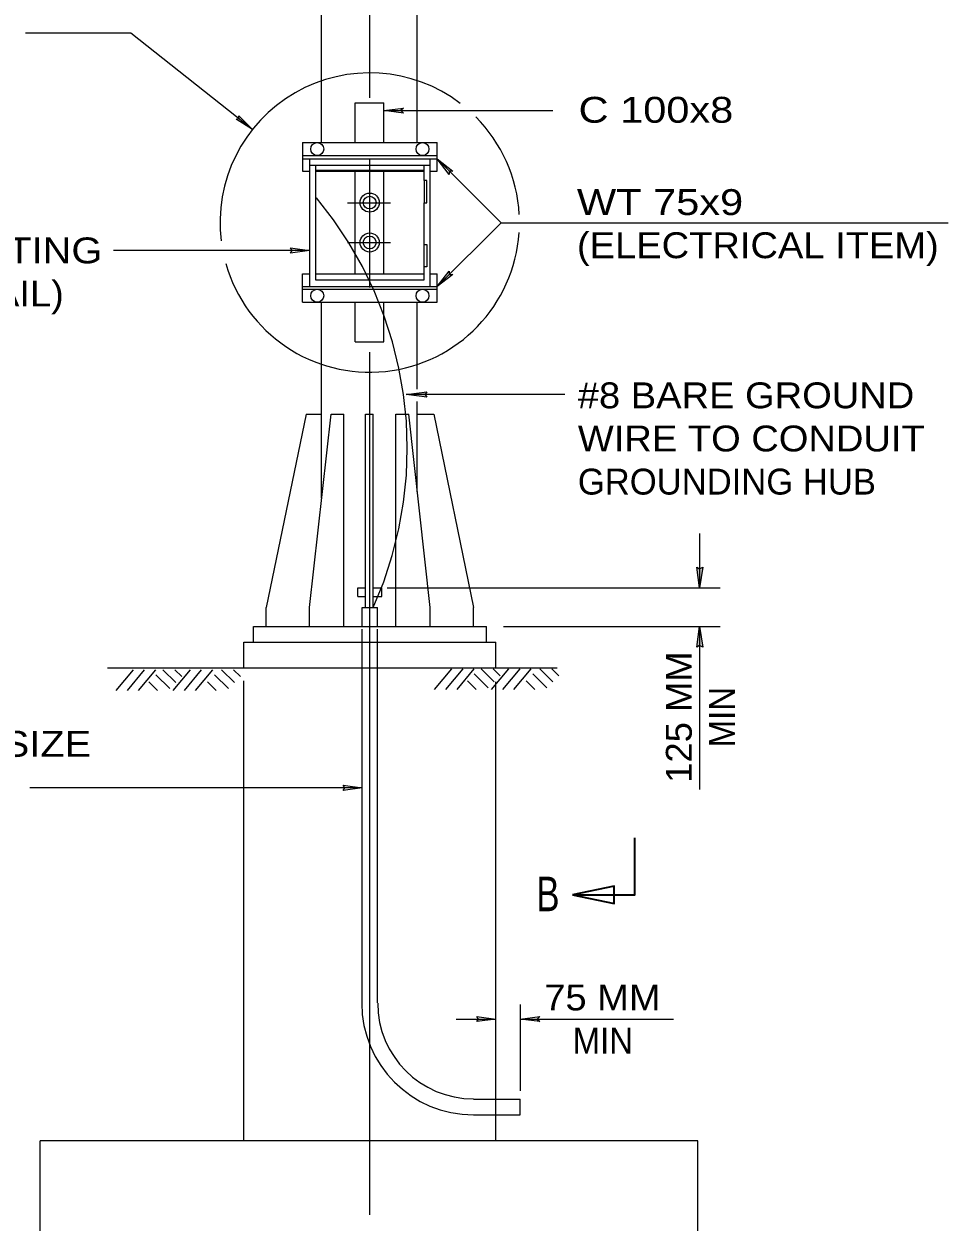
# Model space of a CAD drawing. Extents: x 312601.858 to 312602.699, y 144420.109 to 144420.704.
# Drawn here: x 312601.9631 to 312602.0702, y 144420.232 to 144420.3709 of the extents above; entities that cross this region are included whole.
import ezdxf
from ezdxf.enums import TextEntityAlignment as Align

# ---------------------------------------------------------------- set-up
doc = ezdxf.new("R2010")
doc.units = 0
doc.header["$LTSCALE"] = 0.0012
doc.linetypes.add('LONG_DASH_SHORT_DASH', pattern=[9.9, 6, -1.2, 1.5, -1.2])
doc.linetypes.add('LONG_DASHED', pattern=[7.5, 6, -1.5])
for name, color, linetype, lineweight in [('1', 7, 'Continuous', 25), ('2', 7, 'Continuous', 25), ('39', 7, 'Continuous', 13)]:
    doc.layers.add(name, color=color, linetype=linetype, lineweight=lineweight)

msp = doc.modelspace()

# ---------------------------------------------------------------- hatches: boundary and pattern name
at = {"layer": '39'}
for points in [[(312602.0096, 144420.3279), (312602.0098, 144420.3276), (312602.0074, 144420.3279), (312602.0098, 144420.3282)], [(312602.0414, 144420.3077), (312602.0418, 144420.3079), (312602.0414, 144420.3055), (312602.0411, 144420.3079)], [(312602.0414, 144420.2988), (312602.0411, 144420.2986), (312602.0414, 144420.301), (312602.0418, 144420.2986)]]:
    msp.add_hatch(color=256, dxfattribs=at).paths.add_polyline_path(points)

# ---------------------------------------------------------------- linework, layer by layer
at = {"layer": '1', "linetype": 'LONG_DASH_SHORT_DASH', "lineweight": 13}
for p, q in [((312602.0032, 144420.3623), (312602.0032, 144420.3835)), ((312602.0032, 144420.3403), (312602.0032, 144420.3552)), ((312602.0006, 144420.3501), (312602.0056, 144420.3501)), ((312602.0006, 144420.3455), (312602.0056, 144420.3455)), ((312602.0032, 144420.2328), (312602.0032, 144420.3338))]:
    msp.add_line(p, q, dxfattribs=at)
at = {"layer": '1'}
for p, q in [((312601.9976, 144420.3571), (312601.9976, 144420.3784)), ((312602.0087, 144420.3571), (312602.0087, 144420.3784)), ((312602.0015, 144420.3617), (312602.0048, 144420.3617)), ((312602.0015, 144420.3571), (312602.0015, 144420.3617)), ((312602.0048, 144420.3571), (312602.0048, 144420.3617)), ((312601.9954, 144420.3571), (312602.011, 144420.3571)), ((312601.9954, 144420.3571), (312601.9954, 144420.3538)), ((312602.011, 144420.3538), (312602.011, 144420.3571)), ((312601.9954, 144420.3556), (312602.011, 144420.3556)), ((312601.9954, 144420.3552), (312602.011, 144420.3552)), ((312601.9962, 144420.3552), (312601.9962, 144420.3404)), ((312602.0102, 144420.3404), (312602.0102, 144420.3552)), ((312601.9954, 144420.3538), (312601.9962, 144420.3538)), ((312601.9962, 144420.3545), (312602.0102, 144420.3545)), ((312601.9969, 144420.3545), (312601.9969, 144420.3412)), ((312601.9969, 144420.3538), (312602.0095, 144420.3538)), ((312602.0095, 144420.3527), (312602.0095, 144420.3545)), ((312602.0102, 144420.3538), (312602.011, 144420.3538)), ((312601.9954, 144420.3386), (312601.9954, 144420.3419)), ((312601.9954, 144420.3419), (312601.9962, 144420.3419)), ((312601.9969, 144420.3412), (312602.0095, 144420.3412)), ((312602.0102, 144420.3419), (312602.011, 144420.3419)), ((312602.011, 144420.3386), (312602.011, 144420.3419)), ((312601.9954, 144420.3404), (312602.011, 144420.3404)), ((312601.9954, 144420.3401), (312602.011, 144420.3401)), ((312601.9954, 144420.3386), (312602.011, 144420.3386)), ((312601.9976, 144420.3159), (312601.9976, 144420.3386)), ((312602.0015, 144420.334), (312602.0015, 144420.3386)), ((312602.0048, 144420.334), (312602.0048, 144420.3386)), ((312602.0087, 144420.3285), (312602.0087, 144420.3386)), ((312602.0015, 144420.334), (312602.0048, 144420.334)), ((312602.0087, 144420.3166), (312602.0087, 144420.3271)), ((312601.9958, 144420.3256), (312601.9912, 144420.3032)), ((312601.9958, 144420.3256), (312601.9976, 144420.3256)), ((312601.9987, 144420.3256), (312602.0002, 144420.3256)), ((312602.0002, 144420.301), (312602.0002, 144420.3256)), ((312602.0027, 144420.3256), (312602.0036, 144420.3256)), ((312602.0027, 144420.3032), (312602.0027, 144420.3256)), ((312602.0036, 144420.3032), (312602.0036, 144420.3256)), ((312602.0062, 144420.301), (312602.0062, 144420.3256)), ((312602.0062, 144420.3256), (312602.0077, 144420.3256)), ((312602.0087, 144420.3256), (312602.0106, 144420.3256)), ((312602.0106, 144420.3256), (312602.0152, 144420.3032)), ((312602.0018, 144420.3045), (312602.0018, 144420.3055)), ((312602.0018, 144420.3055), (312602.0027, 144420.3055)), ((312602.0036, 144420.3055), (312602.0046, 144420.3055)), ((312602.0046, 144420.3045), (312602.0046, 144420.3055)), ((312602.0018, 144420.3045), (312602.0027, 144420.3045)), ((312602.0036, 144420.3045), (312602.0046, 144420.3045)), ((312601.9912, 144420.301), (312601.9912, 144420.3032)), ((312601.9962, 144420.301), (312601.9962, 144420.3032)), ((312602.0023, 144420.3032), (312602.0041, 144420.3032)), ((312602.0023, 144420.301), (312602.0023, 144420.3032)), ((312602.0041, 144420.301), (312602.0041, 144420.3032)), ((312602.0102, 144420.301), (312602.0102, 144420.3032)), ((312602.0152, 144420.301), (312602.0152, 144420.3032)), ((312601.9897, 144420.301), (312602.0167, 144420.301)), ((312601.9897, 144420.2992), (312601.9897, 144420.301)), ((312602.0167, 144420.2992), (312602.0167, 144420.301)), ((312601.9886, 144420.2992), (312602.0178, 144420.2992)), ((312601.9886, 144420.2962), (312601.9886, 144420.2992)), ((312602.0178, 144420.2962), (312602.0178, 144420.2992)), ((312601.9728, 144420.2962), (312602.0249, 144420.2962))]:
    msp.add_line(p, q, dxfattribs=at)
at = {"layer": '1', "lineweight": 13}
for p, q in [((312601.9755, 144420.3698), (312601.9633, 144420.3698)), ((312601.9896, 144420.3586), (312601.9755, 144420.3698)), ((312602.0048, 144420.3608), (312602.0244, 144420.3608)), ((312602.011, 144420.3552), (312602.0184, 144420.3478)), ((312602.011, 144420.3404), (312602.0184, 144420.3478)), ((312602.0184, 144420.3478), (312602.0702, 144420.3478)), ((312601.9962, 144420.3446), (312601.9735, 144420.3446)), ((312602.0258, 144420.3279), (312602.0074, 144420.3279)), ((312602.0414, 144420.3118), (312602.0414, 144420.3055)), ((312602.0052, 144420.3055), (312602.0438, 144420.3055)), ((312602.0187, 144420.301), (312602.0438, 144420.301)), ((312602.0414, 144420.301), (312602.0414, 144420.2821)), ((312601.9738, 144420.2936), (312601.9758, 144420.296)), ((312601.9751, 144420.2936), (312601.9771, 144420.296)), ((312601.9764, 144420.2936), (312601.9784, 144420.296)), ((312601.9784, 144420.2954), (312601.98, 144420.2938)), ((312601.9792, 144420.296), (312601.9807, 144420.2945)), ((312601.9804, 144420.2936), (312601.9824, 144420.296)), ((312601.9806, 144420.296), (312601.9814, 144420.2952)), ((312601.9817, 144420.2936), (312601.9837, 144420.296)), ((312601.983, 144420.2936), (312601.985, 144420.296)), ((312601.9852, 144420.2954), (312601.9868, 144420.2938)), ((312601.986, 144420.296), (312601.9875, 144420.2945)), ((312601.9874, 144420.296), (312601.9882, 144420.2952)), ((312602.0107, 144420.2937), (312602.0127, 144420.2961)), ((312602.012, 144420.2937), (312602.014, 144420.2961)), ((312602.0133, 144420.2937), (312602.0153, 144420.2961)), ((312602.0153, 144420.2955), (312602.0169, 144420.2939)), ((312602.0161, 144420.2961), (312602.0176, 144420.2946)), ((312602.0173, 144420.2937), (312602.0193, 144420.2961)), ((312602.0175, 144420.2961), (312602.0183, 144420.2953)), ((312602.0186, 144420.2937), (312602.0206, 144420.2961)), ((312602.0199, 144420.2937), (312602.0219, 144420.2961)), ((312602.0221, 144420.2955), (312602.0237, 144420.2939)), ((312602.0229, 144420.2961), (312602.0244, 144420.2946)), ((312602.0243, 144420.2961), (312602.0251, 144420.2953)), ((312601.9776, 144420.2946), (312601.9786, 144420.2936)), ((312601.9844, 144420.2946), (312601.9854, 144420.2936)), ((312602.0145, 144420.2947), (312602.0155, 144420.2937)), ((312602.0213, 144420.2947), (312602.0223, 144420.2937)), ((312602.0023, 144420.2823), (312601.9638, 144420.2823)), ((312602.0206, 144420.2572), (312602.0206, 144420.2472)), ((312602.0132, 144420.2555), (312602.0178, 144420.2555)), ((312602.0206, 144420.2555), (312602.0384, 144420.2555))]:
    msp.add_line(p, q, dxfattribs=at)
at = {"layer": '1', "linetype": 'LONG_DASHED'}
msp.add_line((312601.9969, 144420.3539), (312602.0095, 144420.3539), dxfattribs=at)
at = {"layer": '1', "linetype": 'LONG_DASHED', "lineweight": 13}
for p, q in [((312602.0015, 144420.3419), (312602.0015, 144420.3538)), ((312602.0048, 144420.3419), (312602.0048, 144420.3538)), ((312601.9969, 144420.3419), (312602.0095, 144420.3419)), ((312602.0023, 144420.2574), (312602.0023, 144420.3007)), ((312602.0041, 144420.2574), (312602.0041, 144420.3007)), ((312601.9886, 144420.2414), (312601.9886, 144420.2947)), ((312602.0178, 144420.2414), (312602.0178, 144420.2946)), ((312602.0152, 144420.2462), (312602.0206, 144420.2462)), ((312602.0206, 144420.2444), (312602.0206, 144420.2462)), ((312602.0152, 144420.2444), (312602.0206, 144420.2444)), ((312601.965, 144420.2234), (312601.965, 144420.2414)), ((312602.0412, 144420.2414), (312601.965, 144420.2414))]:
    msp.add_line(p, q, dxfattribs=at)
at = {"layer": '1', "lineweight": 13}
for points in [[(312602.0071, 144420.3605), (312602.0048, 144420.3608), (312602.0071, 144420.3611), (312602.0068, 144420.3608)], [(312601.988, 144420.3602), (312601.9896, 144420.3586), (312601.9877, 144420.3598), (312601.988, 144420.3599)], [(312602.0124, 144420.3534), (312602.011, 144420.3552), (312602.0128, 144420.3538), (312602.0124, 144420.3538)], [(312601.994, 144420.3449), (312601.9962, 144420.3446), (312601.994, 144420.3443), (312601.9942, 144420.3446)], [(312602.0128, 144420.3418), (312602.011, 144420.3404), (312602.0124, 144420.3422), (312602.0124, 144420.3418)], [(312602.0001, 144420.2826), (312602.0023, 144420.2823), (312602.0001, 144420.282), (312602.0003, 144420.2823)], [(312602.0156, 144420.2558), (312602.0178, 144420.2555), (312602.0156, 144420.2552), (312602.0158, 144420.2555)], [(312602.0229, 144420.2552), (312602.0206, 144420.2555), (312602.0229, 144420.2558), (312602.0226, 144420.2555)]]:
    msp.add_lwpolyline(points, close=True, dxfattribs=at)
at = {"layer": '1'}
msp.add_lwpolyline([(312602.0095, 144420.3412), (312602.0095, 144420.3501), (312602.0098, 144420.3501), (312602.0098, 144420.3527), (312602.0095, 144420.3527), (312602.0095, 144420.3501)], dxfattribs=at)
msp.add_lwpolyline([(312602.0095, 144420.3453), (312602.0098, 144420.3453), (312602.0098, 144420.3427), (312602.0095, 144420.3427)], close=True, dxfattribs=at)
at = {"layer": '1', "linetype": 'LONG_DASHED', "lineweight": 13}
msp.add_lwpolyline([(312601.965, 144420.2234), (312602.0412, 144420.2234), (312602.0412, 144420.2414)], dxfattribs=at)
at = {"layer": '1'}
for centre, radius in [((312601.9971, 144420.35635), 0.00075), ((312602.0093, 144420.35635), 0.00075), ((312602.003181, 144420.350142), 0.00111), ((312602.003181, 144420.350142), 0.00074), ((312602.003181, 144420.345517), 0.00111), ((312602.003181, 144420.345517), 0.00074), ((312601.9971, 144420.33935), 0.00075), ((312602.0093, 144420.33935), 0.00075)]:
    msp.add_circle(centre, radius, dxfattribs=at)
at = {"layer": '1', "lineweight": 13}
for start, end in [(52.76429, 187.07844), (3.14562, 44.8773), (195.9314, 356.15117)]:
    msp.add_arc((312602.003181, 144420.34783), 0.017351, start, end, dxfattribs=at)
at = {"layer": '1', "linetype": 'LONG_DASHED'}
msp.add_arc((312601.962274, 144420.321666), 0.045264, 335.92285, 39.89805, dxfattribs=at)
at = {"layer": '1', "linetype": 'LONG_DASHED', "lineweight": 13}
for radius in [0.012952, 0.011102]:
    msp.add_arc((312602.015208, 144420.257351), radius, 180, 270, dxfattribs=at)
at = {"layer": '2'}
for p, q in [((312601.9962, 144420.3032), (312601.9987, 144420.3256)), ((312602.0102, 144420.3032), (312602.0077, 144420.3256))]:
    msp.add_line(p, q, dxfattribs=at)
at = {"layer": '39'}
for points in [[(312602.0096, 144420.3279), (312602.0098, 144420.3276), (312602.0074, 144420.3279), (312602.0098, 144420.3282)], [(312602.0414, 144420.3077), (312602.0418, 144420.3079), (312602.0414, 144420.3055), (312602.0411, 144420.3079)], [(312602.0414, 144420.2988), (312602.0411, 144420.2986), (312602.0414, 144420.301), (312602.0418, 144420.2986)], [(312602.0315, 144420.2709), (312602.0267, 144420.2699), (312602.0315, 144420.2689)]]:
    msp.add_lwpolyline(points, close=True, dxfattribs=at)
at = {"layer": '39', "lineweight": 35}
msp.add_lwpolyline([(312602.0269, 144420.2699), (312602.0339, 144420.2699), (312602.0339, 144420.2765)], dxfattribs=at)
msp.add_lwpolyline([(312602.0267, 144420.2699), (312602.0315, 144420.2689), (312602.0315, 144420.2709)], close=True, dxfattribs=at)

# ---------------------------------------------------------------- texts
at = {"layer": '1'}
for s, height, width, p in [('(SEE SIGN LIGHTING', 0.003, 1.15, (312601.9258, 144420.3431)), ('ASSEMBLY DETAIL)', 0.003, 1.1, (312601.9258, 144420.3381)), ('#8 BARE GROUND ', 0.003, 1.1, (312602.0273, 144420.3263)), ('WIRE TO CONDUIT', 0.003, 1.1, (312602.0273, 144420.3213)), ('CONDUIT (FOR SIZE', 0.003, 1.15, (312601.9258, 144420.2859)), ('B', 0.004, 0.75, (312602.0225, 144420.268))]:
    msp.add_text(s, height=height, dxfattribs=dict(at, width=width)).set_placement(p)
msp.add_text('GROUNDING HUB', height=0.003, dxfattribs=at).set_placement((312602.0273, 144420.3163))
at = {"layer": '2'}
for s, width, p in [('C 100x8', 1.2, (312602.03635, 144420.3594)), ('75 MM', 1.1, (312602.03015, 144420.2565)), ('MIN', 0.95, (312602.0302, 144420.2515))]:
    msp.add_text(s, height=0.003, dxfattribs=dict(at, width=width)).set_placement(p, align=Align.CENTER)
for s, width, p in [('WT 75x9', 1.2, (312602.0272, 144420.3487)), ('(ELECTRICAL ITEM)', 1.1, (312602.0272, 144420.3437))]:
    msp.add_text(s, height=0.003, dxfattribs=dict(at, width=width)).set_placement(p)
for s, width, p in [('125 MM', 1.05, (312602.0405, 144420.2905)), ('MIN', 0.95, (312602.0455, 144420.2905))]:
    msp.add_text(s, height=0.003, rotation=90, dxfattribs=dict(at, width=width)).set_placement(p, align=Align.CENTER)

doc.saveas('drawing.dxf')
